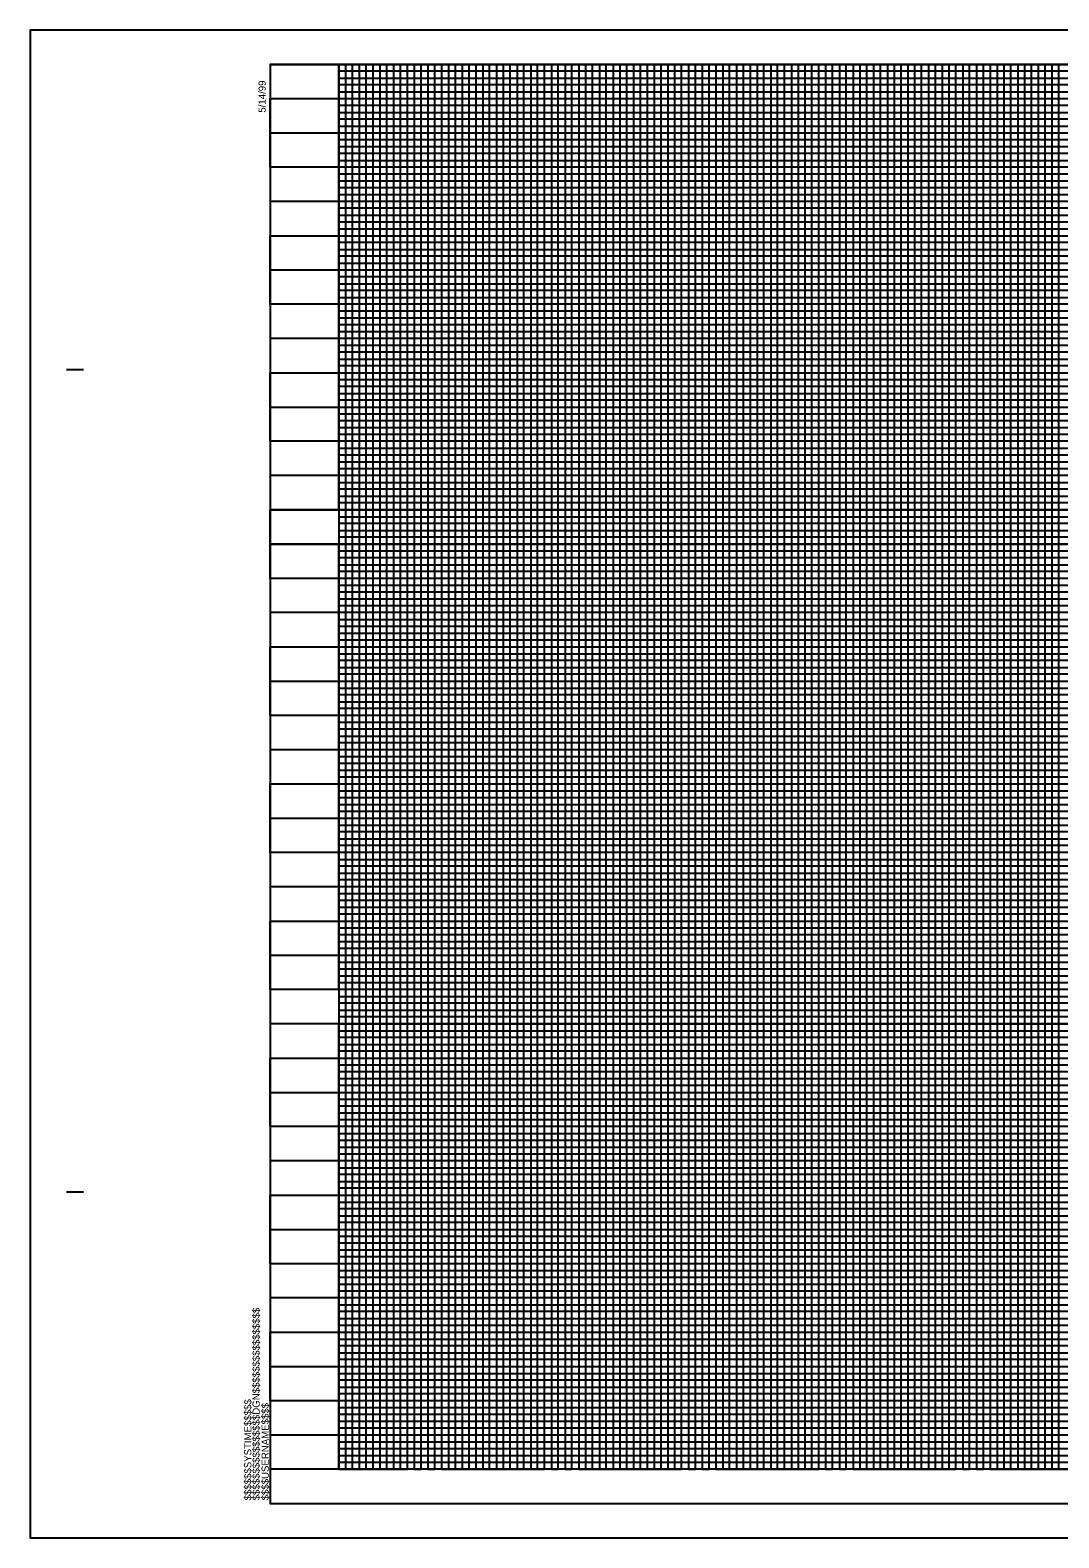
# Model space of a CAD drawing. Extents: x 573058.4 to 573116.8, y -55221.3 to -55199.3.
# Drawn here: x 573078.01 to 573093.01, y -55221.3 to -55199.3 of the extents above; entities that cross this region are included whole.
import ezdxf

# ---------------------------------------------------------------- set-up
doc = ezdxf.new("R2010")
doc.units = 0
for name, color, linetype in [('Sheet Clip Boundary CELL', 7, 'Continuous'), ('Sheet Plot Border Inside CELL', 7, 'Continuous'), ('Sheet Profile CELL', 7, 'Continuous'), ('Sheet Profile Grid Major CELL', 7, 'Continuous'), ('Sheet Profile Grid Middle CELL', 7, 'Continuous'), ('Sheet Profile Grid Minor CELL', 7, 'Continuous')]:
    doc.layers.add(name, color=color, linetype=linetype)

msp = doc.modelspace()

# ---------------------------------------------------------------- linework, layer by layer
at = {"layer": 'Sheet Clip Boundary CELL'}
for points in [[(573082.514, -55199.798), (573107.514, -55199.798), (573107.514, -55204.798), (573110.514, -55204.798), (573110.514, -55206.298), (573082.514, -55206.298)], [(573082.514, -55199.798), (573107.514, -55199.798), (573107.514, -55204.798), (573110.514, -55204.798), (573110.514, -55206.298), (573082.514, -55206.298)], [(573082.514, -55206.798), (573110.514, -55206.798), (573110.514, -55213.298), (573082.514, -55213.298)], [(573082.514, -55206.798), (573110.514, -55206.798), (573110.514, -55213.298), (573082.514, -55213.298)], [(573082.514, -55213.798), (573110.514, -55213.798), (573110.514, -55220.298), (573082.514, -55220.298)], [(573082.514, -55213.798), (573110.514, -55213.798), (573110.514, -55220.298), (573082.514, -55220.298)]]:
    msp.add_lwpolyline(points, close=True, dxfattribs=at)
at = {"layer": 'Sheet Plot Border Inside CELL'}
msp.add_lwpolyline([(573112.014, -55199.298), (573078.014, -55199.298), (573078.014, -55221.298), (573112.014, -55221.298)], close=True, dxfattribs=at)
at = {"layer": 'Sheet Profile CELL'}
for p, q in [((573078.544, -55204.248), (573078.794, -55204.248)), ((573111.514, -55206.298), (573081.514, -55206.298)), ((573111.514, -55206.298), (573081.514, -55206.298)), ((573111.514, -55206.798), (573081.514, -55206.798)), ((573111.514, -55206.798), (573081.514, -55206.798)), ((573111.514, -55213.298), (573081.514, -55213.298)), ((573111.514, -55213.298), (573081.514, -55213.298)), ((573111.514, -55213.798), (573081.514, -55213.798)), ((573111.514, -55213.798), (573081.514, -55213.798)), ((573078.544, -55216.248), (573078.794, -55216.248)), ((573111.514, -55220.298), (573081.514, -55220.298)), ((573081.514, -55220.798), (573081.514, -55220.798)), ((573081.514, -55220.798), (573081.514, -55220.798)), ((573081.514, -55220.798), (573081.514, -55220.798)), ((573081.514, -55220.798), (573081.514, -55220.798)), ((573081.514, -55220.798), (573081.514, -55220.798)), ((573081.514, -55220.798), (573081.514, -55220.798))]:
    msp.add_line(p, q, dxfattribs=at)
msp.add_lwpolyline([(573111.514, -55199.798), (573081.514, -55199.798), (573081.514, -55220.798), (573111.514, -55220.798)], close=True, dxfattribs=at)
msp.add_lwpolyline([(573082.264, -55220.798), (573082.264, -55220.798)], dxfattribs=at)
at = {"layer": 'Sheet Profile Grid Major CELL'}
for points in [[(573081.514, -55199.798), (573082.514, -55199.798), (573082.514, -55220.298), (573083.514, -55220.298), (573083.514, -55199.798), (573084.514, -55199.798), (573084.514, -55220.298), (573085.514, -55220.298), (573085.514, -55199.798), (573086.514, -55199.798), (573086.514, -55220.298), (573087.514, -55220.298), (573087.514, -55199.798), (573088.514, -55199.798), (573088.514, -55220.298), (573089.514, -55220.298), (573089.514, -55199.798), (573090.514, -55199.798), (573090.514, -55220.298), (573091.514, -55220.298), (573091.514, -55199.798), (573092.514, -55199.798), (573092.514, -55220.298), (573093.514, -55220.298)], [(573107.514, -55201.298), (573081.514, -55201.298), (573081.514, -55200.298), (573107.514, -55200.298)], [(573107.514, -55203.298), (573081.514, -55203.298), (573081.514, -55202.298), (573107.514, -55202.298)], [(573111.514, -55205.298), (573081.514, -55205.298), (573081.514, -55204.298), (573107.514, -55204.298)], [(573111.514, -55207.298), (573081.514, -55207.298), (573081.514, -55206.298), (573111.514, -55206.298)], [(573111.514, -55209.298), (573081.514, -55209.298), (573081.514, -55208.298), (573111.514, -55208.298)], [(573111.514, -55211.298), (573081.514, -55211.298), (573081.514, -55210.298), (573111.514, -55210.298)], [(573111.514, -55213.298), (573081.514, -55213.298), (573081.514, -55212.298), (573111.514, -55212.298)], [(573111.514, -55215.298), (573081.514, -55215.298), (573081.514, -55214.298), (573111.514, -55214.298)], [(573111.514, -55217.298), (573081.514, -55217.298), (573081.514, -55216.298), (573111.514, -55216.298)], [(573111.514, -55219.298), (573081.514, -55219.298), (573081.514, -55218.298), (573111.514, -55218.298)]]:
    msp.add_lwpolyline(points, dxfattribs=at)
at = {"layer": 'Sheet Profile Grid Middle CELL'}
for points in [[(573083.014, -55220.298), (573083.014, -55199.798), (573084.014, -55199.798), (573084.014, -55220.298), (573085.014, -55220.298), (573085.014, -55199.798), (573086.014, -55199.798), (573086.014, -55220.298), (573087.014, -55220.298), (573087.014, -55199.798), (573088.014, -55199.798), (573088.014, -55220.298), (573089.014, -55220.298), (573089.014, -55199.798), (573090.014, -55199.798), (573090.014, -55220.298), (573091.014, -55220.298), (573091.014, -55199.798), (573092.014, -55199.798), (573092.014, -55220.298), (573093.014, -55220.298), (573093.014, -55199.798), (573094.014, -55199.798)], [(573081.514, -55200.798), (573107.514, -55200.798)], [(573107.514, -55201.798), (573081.514, -55201.798), (573081.514, -55202.798), (573107.514, -55202.798)], [(573107.514, -55203.798), (573081.514, -55203.798), (573081.514, -55204.798), (573111.514, -55204.798)], [(573111.514, -55205.798), (573081.514, -55205.798), (573081.514, -55206.798), (573111.514, -55206.798)], [(573111.514, -55207.798), (573081.514, -55207.798), (573081.514, -55208.798), (573111.514, -55208.798)], [(573111.514, -55209.798), (573081.514, -55209.798), (573081.514, -55210.798), (573111.514, -55210.798)], [(573111.514, -55211.798), (573081.514, -55211.798), (573081.514, -55212.798), (573111.514, -55212.798)], [(573111.514, -55213.798), (573081.514, -55213.798), (573081.514, -55214.798), (573111.514, -55214.798)], [(573111.514, -55215.798), (573081.514, -55215.798), (573081.514, -55216.798), (573111.514, -55216.798)], [(573111.514, -55217.798), (573081.514, -55217.798), (573081.514, -55218.798), (573111.514, -55218.798)], [(573111.514, -55219.798), (573081.514, -55219.798)]]:
    msp.add_lwpolyline(points, dxfattribs=at)
at = {"layer": 'Sheet Profile Grid Minor CELL'}
for p, q in [((573107.514, -55203.398), (573082.514, -55203.398)), ((573082.514, -55203.398), (573082.514, -55203.498)), ((573082.514, -55203.498), (573107.514, -55203.498)), ((573107.514, -55203.898), (573082.514, -55203.898))]:
    msp.add_line(p, q, dxfattribs=at)
for points in [[(573082.614, -55199.798), (573082.714, -55199.798), (573082.814, -55199.798), (573082.914, -55199.798), (573083.114, -55199.798), (573082.453, -55199.798), (573082.553, -55199.798), (573081.714, -55199.798), (573081.814, -55199.798), (573081.914, -55199.798), (573082.114, -55199.798), (573082.214, -55199.798), (573082.314, -55199.798), (573082.414, -55199.798), (573082.614, -55199.798), (573082.614, -55220.298), (573082.714, -55220.298), (573082.714, -55199.798), (573082.814, -55199.798), (573082.814, -55220.298), (573082.914, -55220.298), (573082.914, -55199.798), (573083.114, -55199.798), (573083.114, -55220.298), (573083.214, -55220.298), (573083.214, -55199.798), (573083.314, -55199.798), (573083.314, -55220.298), (573083.414, -55220.298), (573083.414, -55199.798), (573083.614, -55199.798), (573083.614, -55220.298), (573083.714, -55220.298), (573083.714, -55199.798), (573083.814, -55199.798), (573083.814, -55220.298), (573083.914, -55220.298), (573083.914, -55199.798), (573084.114, -55199.798), (573084.114, -55220.298), (573084.214, -55220.298), (573084.214, -55199.798), (573084.314, -55199.798), (573084.314, -55220.298), (573084.414, -55220.298), (573084.414, -55199.798), (573084.614, -55199.798), (573084.614, -55220.298), (573084.714, -55220.298), (573084.714, -55199.798), (573084.814, -55199.798), (573084.814, -55220.298), (573084.914, -55220.298), (573084.914, -55199.798), (573085.114, -55199.798), (573085.114, -55220.298), (573085.214, -55220.298), (573085.214, -55199.798), (573085.314, -55199.798), (573085.314, -55220.298), (573085.414, -55220.298), (573085.414, -55199.798), (573085.614, -55199.798), (573085.614, -55220.298), (573085.714, -55220.298), (573085.714, -55199.798), (573085.814, -55199.798), (573085.814, -55220.298)], [(573107.514, -55199.898), (573082.514, -55199.898), (573082.514, -55199.998), (573107.514, -55199.998)], [(573085.814, -55220.298), (573085.914, -55220.298), (573085.914, -55199.798), (573086.114, -55199.798), (573086.114, -55220.298), (573086.214, -55220.298), (573086.214, -55199.798), (573086.314, -55199.798), (573086.314, -55220.298), (573086.414, -55220.298), (573086.414, -55199.798), (573086.614, -55199.798), (573086.614, -55220.298), (573086.714, -55220.298), (573086.714, -55199.798), (573086.714, -55199.798), (573086.814, -55199.798), (573086.814, -55220.298), (573086.914, -55220.298), (573086.914, -55199.798), (573087.114, -55199.798), (573087.114, -55220.298), (573087.214, -55220.298), (573087.214, -55199.798), (573087.314, -55199.798), (573087.314, -55220.298), (573087.414, -55220.298), (573087.414, -55199.798), (573087.614, -55199.798), (573087.614, -55220.298), (573087.714, -55220.298), (573087.714, -55199.798), (573087.814, -55199.798), (573087.814, -55220.298), (573087.914, -55220.298), (573087.914, -55199.798), (573088.114, -55199.798), (573088.114, -55220.298), (573088.214, -55220.298), (573088.214, -55199.798), (573088.314, -55199.798), (573088.314, -55220.298), (573088.414, -55220.298), (573088.414, -55199.798), (573088.614, -55199.798), (573088.614, -55220.298), (573088.714, -55220.298), (573088.714, -55199.798), (573088.814, -55199.798), (573088.814, -55220.298), (573088.914, -55220.298), (573088.914, -55199.798), (573089.114, -55199.798), (573089.114, -55220.298), (573089.414, -55220.298), (573089.414, -55199.798), (573089.614, -55199.798), (573089.614, -55220.298), (573089.714, -55220.298), (573089.714, -55199.798), (573089.814, -55199.798), (573089.814, -55220.298), (573089.914, -55220.298), (573089.914, -55199.798), (573090.114, -55199.798), (573090.114, -55220.298), (573090.214, -55220.298), (573090.214, -55199.798), (573090.314, -55199.798), (573090.314, -55220.298), (573090.414, -55220.298), (573090.414, -55199.798), (573090.614, -55199.798), (573090.614, -55220.298), (573090.714, -55220.298), (573090.714, -55199.798), (573090.814, -55199.798), (573090.814, -55220.298), (573090.914, -55220.298), (573090.914, -55199.798), (573091.114, -55199.798), (573091.114, -55220.298), (573091.214, -55220.298), (573091.214, -55199.798), (573091.314, -55199.798), (573091.314, -55220.298), (573091.414, -55220.298), (573091.414, -55199.798), (573091.614, -55199.798), (573091.614, -55220.298), (573091.714, -55220.298), (573091.714, -55199.798), (573091.814, -55199.798), (573091.814, -55220.298), (573091.914, -55220.298), (573091.914, -55199.798), (573092.114, -55199.798), (573092.114, -55220.298)], [(573089.214, -55199.798), (573089.214, -55220.298), (573089.314, -55220.298), (573089.314, -55199.798)], [(573089.214, -55199.81), (573089.214, -55220.298), (573089.314, -55220.298), (573089.314, -55199.81)], [(573092.214, -55199.798), (573092.214, -55220.298), (573092.314, -55220.298), (573092.314, -55199.798), (573092.414, -55199.798), (573092.414, -55220.298), (573092.614, -55220.298), (573092.614, -55199.798), (573092.714, -55199.798), (573092.714, -55220.298), (573092.814, -55220.298), (573092.814, -55199.798), (573092.914, -55199.798), (573092.914, -55220.298)], [(573107.514, -55200.098), (573082.514, -55200.098), (573082.514, -55200.198), (573107.514, -55200.198)], [(573107.514, -55200.398), (573082.514, -55200.398), (573082.514, -55200.498), (573107.514, -55200.498)], [(573107.514, -55200.598), (573082.514, -55200.598), (573082.514, -55200.698), (573107.514, -55200.698)], [(573107.514, -55200.898), (573082.514, -55200.898), (573082.514, -55200.998), (573107.514, -55200.998)], [(573107.514, -55201.098), (573082.514, -55201.098), (573082.514, -55201.198), (573107.514, -55201.198)], [(573107.514, -55201.398), (573082.514, -55201.398), (573082.514, -55201.498), (573107.514, -55201.498)], [(573107.514, -55201.598), (573082.514, -55201.598), (573082.514, -55201.698), (573107.514, -55201.698)], [(573107.514, -55201.898), (573082.514, -55201.898), (573082.514, -55201.998), (573107.514, -55201.998)], [(573107.514, -55202.098), (573082.514, -55202.098), (573082.514, -55202.198), (573107.514, -55202.198)], [(573107.514, -55202.398), (573082.514, -55202.398), (573082.514, -55202.498), (573107.514, -55202.498)], [(573107.514, -55202.598), (573082.514, -55202.598), (573082.514, -55202.598), (573082.514, -55202.998), (573107.514, -55202.998)], [(573082.514, -55202.698), (573107.514, -55202.698)], [(573107.514, -55202.898), (573082.514, -55202.898)], [(573107.514, -55203.098), (573082.514, -55203.098), (573082.514, -55203.198), (573107.514, -55203.198)], [(573107.514, -55203.598), (573082.514, -55203.598), (573082.514, -55203.698), (573107.514, -55203.698)], [(573107.514, -55203.998), (573082.514, -55203.998), (573082.514, -55204.098), (573107.514, -55204.098)], [(573107.514, -55204.198), (573082.514, -55204.198)], [(573082.514, -55204.398), (573107.514, -55204.398)], [(573107.514, -55204.498), (573082.514, -55204.498), (573082.514, -55204.598), (573107.514, -55204.598)], [(573107.514, -55204.698), (573082.514, -55204.698), (573082.514, -55204.898), (573110.514, -55204.898)], [(573110.514, -55204.998), (573082.514, -55204.998), (573082.514, -55205.098), (573110.514, -55205.098)], [(573110.514, -55205.198), (573082.514, -55205.198), (573082.514, -55205.398), (573110.514, -55205.398)], [(573110.514, -55205.498), (573082.514, -55205.498), (573082.514, -55205.598), (573110.514, -55205.598)], [(573110.514, -55205.698), (573082.514, -55205.698), (573082.514, -55205.898), (573110.514, -55205.898)], [(573110.514, -55205.998), (573082.514, -55205.998), (573082.514, -55206.098), (573110.514, -55206.098)], [(573110.514, -55206.198), (573082.514, -55206.198), (573082.514, -55206.398), (573110.514, -55206.398)], [(573110.514, -55206.498), (573082.514, -55206.498), (573082.514, -55206.598), (573110.514, -55206.598)], [(573110.514, -55206.698), (573082.514, -55206.698), (573082.514, -55206.898), (573110.514, -55206.898)], [(573110.514, -55206.998), (573082.514, -55206.998), (573082.514, -55207.098), (573110.514, -55207.098)], [(573110.514, -55207.198), (573082.514, -55207.198), (573082.514, -55207.398), (573110.514, -55207.398)], [(573110.514, -55207.498), (573082.514, -55207.498), (573082.514, -55207.598), (573110.514, -55207.598)], [(573110.514, -55207.698), (573082.514, -55207.698), (573082.514, -55207.898), (573110.514, -55207.898)], [(573110.514, -55207.998), (573082.514, -55207.998), (573082.514, -55208.098), (573110.514, -55208.098)], [(573110.514, -55208.198), (573082.514, -55208.198), (573082.514, -55208.398), (573110.514, -55208.398)], [(573110.514, -55208.498), (573082.514, -55208.498), (573082.514, -55208.598), (573110.514, -55208.598)], [(573110.514, -55208.698), (573082.514, -55208.698), (573082.514, -55208.898), (573110.514, -55208.898)], [(573110.514, -55208.998), (573082.514, -55208.998), (573082.514, -55209.098), (573110.514, -55209.098)], [(573110.514, -55209.198), (573082.514, -55209.198), (573082.514, -55209.398), (573110.514, -55209.398)], [(573110.514, -55209.498), (573082.514, -55209.498), (573082.514, -55209.598), (573110.514, -55209.598)], [(573110.514, -55209.698), (573082.514, -55209.698), (573082.514, -55209.898), (573110.514, -55209.898)], [(573110.514, -55209.998), (573082.514, -55209.998), (573082.514, -55210.098), (573110.514, -55210.098)], [(573110.514, -55210.198), (573082.514, -55210.198)], [(573082.514, -55210.398), (573110.514, -55210.398)], [(573110.514, -55210.498), (573082.514, -55210.498), (573082.514, -55210.598), (573110.514, -55210.598)], [(573110.514, -55210.698), (573082.514, -55210.698), (573082.514, -55210.898), (573110.514, -55210.898)], [(573110.514, -55210.998), (573082.514, -55210.998), (573082.514, -55211.098), (573110.514, -55211.098)], [(573110.514, -55211.198), (573082.514, -55211.198), (573082.514, -55211.398), (573110.514, -55211.398)], [(573110.514, -55211.498), (573082.514, -55211.498), (573082.514, -55211.598), (573110.514, -55211.598)], [(573110.514, -55211.698), (573082.514, -55211.698), (573082.514, -55211.898), (573110.514, -55211.898)], [(573110.514, -55211.998), (573082.514, -55211.998), (573082.514, -55212.098), (573110.514, -55212.098)], [(573110.514, -55212.198), (573082.514, -55212.198), (573082.514, -55212.398), (573110.514, -55212.398)], [(573110.514, -55212.498), (573082.514, -55212.498), (573082.514, -55212.598), (573110.514, -55212.598)], [(573110.514, -55212.698), (573082.514, -55212.698), (573082.514, -55212.898), (573110.514, -55212.898)], [(573110.514, -55212.998), (573082.514, -55212.998), (573082.514, -55213.098), (573110.514, -55213.098)], [(573110.514, -55213.198), (573082.514, -55213.198), (573082.514, -55213.398), (573110.514, -55213.398)], [(573110.514, -55213.498), (573082.514, -55213.498), (573082.514, -55213.598), (573110.514, -55213.598)], [(573110.514, -55213.698), (573082.514, -55213.698), (573082.514, -55213.898), (573110.514, -55213.898)], [(573110.514, -55213.998), (573082.514, -55213.998), (573082.514, -55214.098), (573110.514, -55214.098)], [(573110.514, -55214.198), (573082.514, -55214.198), (573082.514, -55214.398), (573110.514, -55214.398)], [(573110.514, -55214.498), (573082.514, -55214.498), (573082.514, -55214.598), (573110.514, -55214.598)], [(573110.514, -55214.698), (573082.514, -55214.698), (573082.514, -55214.898), (573110.514, -55214.898)], [(573110.514, -55214.998), (573082.514, -55214.998), (573082.514, -55215.098), (573110.514, -55215.098)], [(573110.514, -55215.198), (573082.514, -55215.198), (573082.514, -55215.398), (573110.514, -55215.398)], [(573110.514, -55215.498), (573082.514, -55215.498), (573082.514, -55215.598), (573110.514, -55215.598)], [(573110.514, -55215.698), (573082.514, -55215.698), (573082.514, -55215.898), (573110.514, -55215.898)], [(573110.514, -55215.998), (573082.514, -55215.998), (573082.514, -55216.098), (573110.514, -55216.098)], [(573110.514, -55216.198), (573082.514, -55216.198)], [(573082.514, -55216.398), (573110.514, -55216.398)], [(573110.514, -55216.498), (573082.514, -55216.498), (573082.514, -55216.598), (573110.514, -55216.598)], [(573110.514, -55216.698), (573082.514, -55216.698)], [(573082.514, -55216.898), (573110.514, -55216.898)], [(573110.514, -55216.998), (573082.514, -55216.998), (573082.514, -55217.098), (573110.514, -55217.098)], [(573110.514, -55217.198), (573082.514, -55217.198), (573082.514, -55217.398), (573110.514, -55217.398)], [(573110.514, -55217.498), (573082.514, -55217.498), (573082.514, -55217.598), (573110.514, -55217.598)], [(573110.514, -55217.698), (573082.514, -55217.698), (573082.514, -55217.898), (573110.514, -55217.898)], [(573110.514, -55217.998), (573082.514, -55217.998), (573082.514, -55218.098), (573110.514, -55218.098)], [(573110.514, -55218.198), (573082.514, -55218.198), (573082.514, -55218.398), (573110.514, -55218.398)], [(573110.514, -55218.498), (573082.514, -55218.498), (573082.514, -55218.598), (573110.514, -55218.598)], [(573110.514, -55218.698), (573082.514, -55218.698), (573082.514, -55218.898), (573110.514, -55218.898)], [(573110.514, -55218.998), (573082.514, -55218.998), (573082.514, -55219.098), (573110.514, -55219.098)], [(573110.514, -55219.198), (573082.514, -55219.198), (573082.514, -55219.398), (573110.514, -55219.398)], [(573110.514, -55219.498), (573082.514, -55219.498), (573082.514, -55219.598), (573110.514, -55219.598)], [(573110.514, -55219.698), (573082.514, -55219.698), (573082.514, -55219.898), (573110.514, -55219.898)], [(573110.514, -55219.998), (573082.514, -55219.998), (573082.514, -55220.098), (573110.514, -55220.098)], [(573110.514, -55220.198), (573082.514, -55220.198)]]:
    msp.add_lwpolyline(points, dxfattribs=at)

# ---------------------------------------------------------------- texts
at = {"layer": 'Sheet Profile CELL'}
for s, p in [('5/14/99', (573081.449, -55200.502)), ('$$$$$$$$$$$$$$$$DGN$$$$$$$$$$$$$$$$', (573081.361, -55220.751)), ('$$$$$$SYSTIME$$$$$', (573081.24, -55220.751)), ('$$$$USERNAME$$$$', (573081.493, -55220.751))]:
    msp.add_text(s, height=0.105, rotation=90, dxfattribs=at).set_placement(p)

doc.saveas('drawing.dxf')
